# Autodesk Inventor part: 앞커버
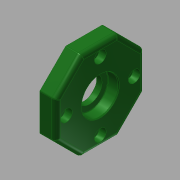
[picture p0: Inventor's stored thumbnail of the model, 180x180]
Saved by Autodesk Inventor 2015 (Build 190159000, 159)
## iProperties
Created: 2015-11
Part Number: 앞커버
Material: 알루미늄 6061
Document SubType Name: Modeling
Designer: mduedu
Density: 1 g/cm^3
Appearance: 매끄러움 - 짙은 산림 녹색
Author: mduedu
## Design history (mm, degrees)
sketch "스케치5" dims "d66" = 60
  geometry: L1 (12.426, 30)-(30, 12.426); L2 (30, 12.426)-(30, -12.426); L3 (30, -12.426)-(12.426, -30); L4 (12.426, -30)-(-12.426, -30); L5 (-12.426, -30)-(-30, -12.426); L6 (-30, -12.426)-(-30, 12.426); L7 (-30, 12.426)-(-12.426, 30); L8 (-12.426, 30)-(12.426, 30); 4 further points
  constraints: 16 end point, 2 coincident, 2 vertical alignment, 1 midpoint, 19 other
extrude "돌출2" new body sketch "스케치5" distance "d67" = 11; taper "d68" = 0 deg
sketch "스케치6"
  geometry: C1 r 16 at (0, 0); 1 further point
  constraints: 1 centre point, 1 coincident
  dimensions: "d69" = 32 diameter of C1
extrude "돌출3" join sketch "스케치6" distance "d70" = 3; taper "d71" = 0 deg
hole "구멍7" diameter "d98" = 25; stored, may be unused: countersink angle "d102" = 90 deg, drill point angle "d104" = 0 deg; dims "d96" = 10, "d97" = 10, "d99" = 6, "d100" = 4, "d101" = 2, "d103" = 3
hole "구멍8" diameter "d107" = 25; stored, may be unused: countersink angle "d111" = 90 deg, drill point angle "d113" = 0 deg; dims "d108" = 6, "d109" = 4, "d110" = 2, "d112" = 7.3, "d143" = 10, "d144" = 10
hole "구멍9" diameter "d116" = 17; stored, may be unused: countersink angle "d120" = 90 deg, drill point angle "d122" = 0 deg; dims "d114" = 10, "d115" = 10, "d117" = 6, "d118" = 4, "d119" = 2, "d121" = 7.7
chamfer "모따기2" distance "d123" = 0.7; stored, may be unused: second distance "d124" = 2, angle "d125" = 30 deg
fillet "모깎기11" dims "d126" = 0.3
fillet "모깎기12" dims "d127" = 1
fillet "모깎기13" dims "d128" = 3
fillet "모깎기14" dims "d129" = 3
fillet "모깎기15" dims "d130" = 0.3
sketch "스케치8" dims "d131" = 46
  geometry: 3 further points
  constraints: 2 vertical alignment, 1 coincident, 2 other
hole "구멍10" sketch "스케치8" at (0, 23) diameter "d132" = 4.5; stored, may be unused: countersink angle "d136" = 90 deg, drill point angle "d138" = 0 deg; dims "d133" = 6, "d134" = 8, "d135" = 4.6, "d137" = 7.7
node "솔리드2"
pattern_circular "원형 패턴4" dims angle "d140" = 360 deg
